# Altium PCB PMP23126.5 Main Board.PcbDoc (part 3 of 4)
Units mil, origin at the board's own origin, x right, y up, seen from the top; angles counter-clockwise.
Board outline 7480.32 x 4667 mil, 6 copper layers (Top Layer, Signal Layer 1, Signal Layer 2, Signal Layer 3, Signal Layer 4, Bottom Layer), stack 65.8 mil thick; 166 components, 83 nets, 633 pads, 4418 vias.
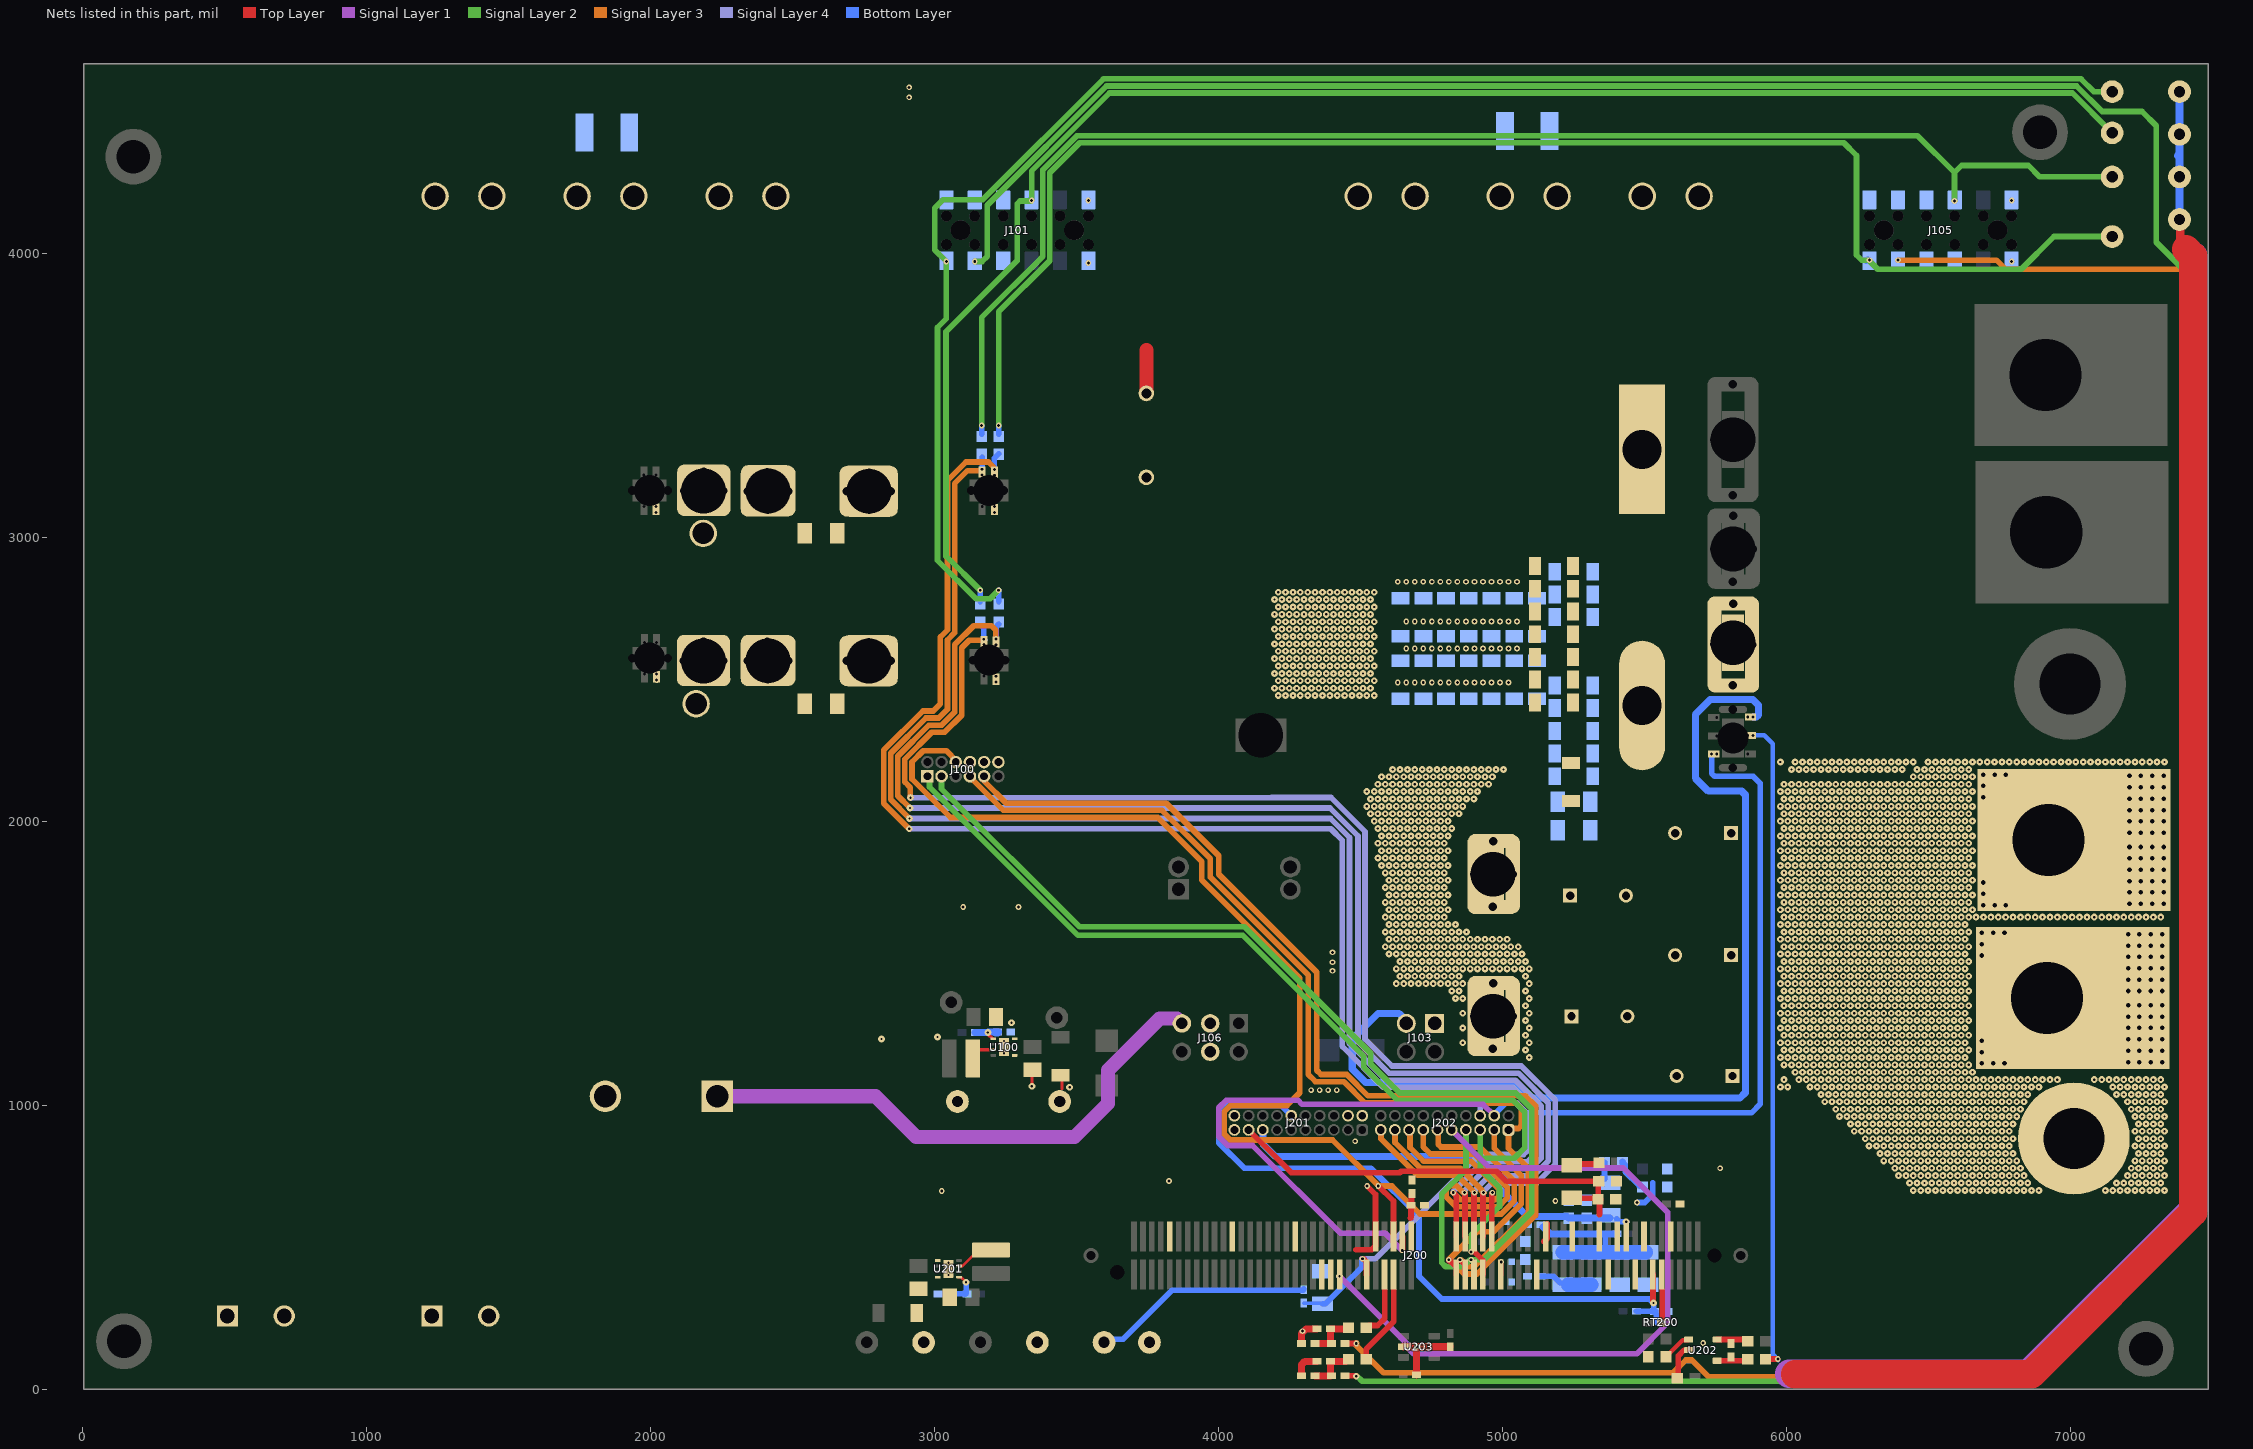
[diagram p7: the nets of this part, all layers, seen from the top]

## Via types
v1: diameter 24, hole 8, Top Layer to Bottom Layer, 3810 vias
v2: diameter 32, hole 16, Top Layer to Bottom Layer, 232 vias
v3: diameter 24, hole 8, Top Layer to Bottom Layer, tented top, 210 vias
v4: diameter 20, hole 10, Top Layer to Bottom Layer, 76 vias
v5: diameter 20, hole 10, Top Layer to Bottom Layer, tented top, 57 vias
v6: diameter 24, hole 8, Top Layer to Bottom Layer, tented both sides, 29 vias
v7: diameter 19.68, hole 7.87, Top Layer to Bottom Layer, 4 vias

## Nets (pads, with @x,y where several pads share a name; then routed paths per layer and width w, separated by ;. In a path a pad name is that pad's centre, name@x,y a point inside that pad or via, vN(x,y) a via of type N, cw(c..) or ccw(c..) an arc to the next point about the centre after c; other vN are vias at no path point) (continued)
Iout_SNS: C300.1 C301.1 C302.1 C303.1 C304.1 C305.1 C306.1 C307.1 C308.1 C309.1 C310.2 C311.2 C312.2 C313.2 C314.2 C315.1 C316.1 C317.1 C318.1 C319.1 C320.1 C321.1 C322.1 C323.1 C324.1 C325.1 C326.1 C327.1 C328.1 C329.1 C330.1 C331.1 C332.1 C333.1 C334.1 L100.2 pad.1@4900,1815 pad.1@4965,1700 pad.1@4965,1815 pad.1@4966,1932 pad.1@5035,1815 pad.1@5745,2625 pad.1@5810,2480 pad.1@5810,2630 pad.1@5811,2768 pad.1@5862,2303.04 pad.1@5877.57,2622.15 R102.2 R103.2 R226.1 | length 2304
  Top Layer w20: R226.1@5924.86,108.3 v4(5968.17,108.3)
  Bottom Layer w16: pad.1@5880,2305 5920,2305 5950,2275 5950,125 v4@5970,105
  other v4: 5880,2303.04
  other v5: 4660,2610 4690,2610 4720,2610 4750,2610 4780,2610 4810,2610 4840,2610 4870,2610 4900,2610 4930,2610 4960,2610 4990,2610 5020,2610 5050,2610 4660,2705 4690,2705 4720,2705 4750,2705 4780,2705 4810,2705 4840,2705 4870,2705 4900,2705 4930,2705 4960,2705 4990,2705 5020,2705 5050,2705
LEG1_FLT: J101.3 R200.2 | length 11737.8
  Top Layer w20: R200.2@4444.54,49.24 v6@4483.91,49.24
  Signal Layer 2 w20: v4(3141,3972) 3167,3972 3185,3990 3185,4170.36 3604.64,4590 7020,4590 7110,4500 7250,4500 7300,4450 7300,4040 7455,3885 7455,615 6870,30 4505,30 v6@4485,50
  other v6: 4484,48
LEG1_HS: J200.49 J202.17 pad.1@3172.91,2623.88 R105.2 | length 5044.8
  Top Layer w20: J200.49@4929.94,539.86 4929.94,692.57 v4(4931.63,694.27)
  Signal Layer 3 w20: v6(2914.78,2084.78) 2914.01,2085.54 2914.01,2120.49 2895,2139.5 2895,2220.36 2989.64,2315 3035,2315 3095,2375 3095,2612.43 3121.57,2639 pad.1@3170.41,2639 ; J202.17@4620,915 4620,870.54 4710.54,780 4849.76,780 4925.13,704.62 4925.13,700.76 v4(4931.63,694.27)
  Signal Layer 4 w20: v6(2914.78,2084.78) 4186.53,2084.78 4186.75,2085 4395,2085 4515,1965 4515,1235 4610,1140 5065,1140 5185,1020 5185,795 5118.25,728.25 4961.75,728.25 4935,701.5 v4@4935,700 ; pad.1@3172.91,2623.88 pad.1@3172.91,2642 ; pad.1@3172.91,2642.1 v6(3173,2642) pad.1@3175,2640
  Bottom Layer w20: R105.2@3165,2690 3173,2682 v6(3173,2642)
LEG1_HS1: J101.8 LEG1_HS.1 R105.1 | length 5683.7
  Signal Layer 2 w20: v4(3160,2815) 3040,2935 3040,3725 3290,3975 3290,4175 3300,4185 v4@3340,4185 ; v4(3341,4187) 3341,4291 3615,4565 7005,4565 LEG1_HS.1@7140,4430
  Bottom Layer w20: R105.1@3160,2775 v4(3160,2815) ; J101.8@3339.25,4194.75 J101.8@3342,4192
LEG1_HS_Fault: J101.6
LEG1_HS_OC: J101.4
LEG1_HS_TEMP: J101.2
LEG1_LS: J200.51 J202.19 pad.1@3215.96,2622.88 R104.1 | length 5164.4
  Top Layer w20: J200.51@4898.44,539.86 v4@4898.44,692.57
  Signal Layer 3 w20: v6(2913.08,2048.29) 2870,2091.37 2870,2230.71 2979.29,2340 3024.64,2340 3070,2385.36 3070,2622.78 3137.22,2690 3200,2690 3215,2675 pad.1@3215,2650 ; J202.19@4570,910 4570.83,909.17 4570.83,884.17 4637,818 4637.18,818 4653,802.18 4700.18,755 4839.4,755 v4(4900.13,694.27)
  Signal Layer 4 w20: v6(2913.08,2048.29) 4391.71,2048.29 4490,1950 4490,1224.64 4599.64,1115 5054.64,1115 ; v4@4900,695 4900,701.85 4951.4,753.25 5107.89,753.25 5160,805.36 5160,1009.64 5054.82,1114.82 5054.64,1114.82
  Bottom Layer w20: v4(3215.96,2643) 3215.96,2685.96 R104.1@3225,2695
LEG1_LS1: J101.1 LEG1_LS.1 R104.2 | length 5940.3
  Signal Layer 2 w20: v4(3225,2815) 3195,2785 3145,2785 3010,2920 3010,3740 3041,3771 v4(3041,3972) 3000,4013 3000,4160 3030,4190 3169.29,4190 3594.29,4615 7035,4615 7080,4570 LEG1_LS.1@7140,4570
  Bottom Layer w20: R104.2@3225,2775 v4(3225,2815)
LEG1_LS_OC: J101.5
LEG2_FLT: J105.3 R203.2 | length 7679.5
  Top Layer w20: R203.2@4444.54,163.42 v4@4479.98,163.42
  Signal Layer 3 w20: v4@4485,165 4485,155 4580,60 5600,60 5645,105 5665,105 5725,45 6854.64,45 7430,620.36 7430,3929.64 7414.64,3945 6770,3945 6738,3977 v4(6391,3977)
  other v4: 4483.91,163.42
LEG2_HS: J200.53 J202.13 pad.1@3166.91,3220.88 R108.2 | length 6028.7
  Top Layer w20: v4(4864.7,694.27) 4866.94,692.02 J200.53@4866.94,539.86
  Signal Layer 3 w20: v6(2911.59,2011.59) 2845,2078.18 2845,2241.07 2968.93,2365 3014.29,2365 3045,2395.71 3045,2640 3070,2665 3070,3190.43 3115.57,3236 pad.1@3164.41,3236 ; J202.13@4715.14,910 4720,905.14 4720,855 4745,830 4898.1,830 5015,713.1 5015,675.43 4983.84,644.27 4835.73,644.27 4800.33,679.67 4800.33,704.62 4814.98,719.27 4835.69,719.27 4860.69,694.27 v4(4864.7,694.27)
  Signal Layer 4 w20: v6(2911.59,2011.59) 4393.05,2011.59 4460,1944.64 4460,1219.29 4589.29,1090 5043.93,1090 5135,998.93 5135,815.71 5097.54,778.25 4941.04,778.25 4865,702.21 v4@4865,695
  Bottom Layer w20: pad.1@3166.91,3220.88 v4(3166.91,3241) R108.2@3166.91,3283.1
LEG2_HS1: J105.8 LEG2_HS.1 R108.1 | length 5014.3
  Signal Layer 2 w20: v4(3165,3395) 3165,3775 3380,3990 3380,4294.64 3500.36,4415 6460,4415 6590,4285 ; v4(6590,4185) 6590,4285 ; LEG2_HS.1@7145,4270 6890,4270 6850,4310 6615,4310 6590,4285
  Bottom Layer w20: R108.1@3165,3365 v4(3165,3395)
LEG2_HS_Fault: J105.6
LEG2_HS_OC: J105.4
LEG2_HS_TEMP: J105.2
LEG2_LS: J200.55 J202.15 pad.1@3209.96,3219.88 R106.1 | length 5987.2
  Top Layer w20: v4(4825.33,694.27) 4835.45,684.15 J200.55@4835.45,539.86
  Signal Layer 3 w20: v6(2910,1975) 2820,2065 2820,2251.42 2958.58,2390 2995,2390 3020,2415 3020,2650.36 3045,2675.36 3045,3200.78 3110.22,3266 3189,3266 pad.1@3210,3245 ; J202.15@4665,905 4672.95,897.05 4672.95,852.95 4720.89,805 4887.75,805 4988.13,704.62 4988.13,683.91 4973.48,669.27 4850.33,669.27 v4(4825.33,694.27)
  Signal Layer 4 w20: v6(2910,1975) 4394.29,1975 4435,1934.29 4435,1208.93 4578.93,1065 5033.58,1065 5110,988.58 5110,826.07 5087.18,803.25 4930.69,803.25 4825,697.56 v4@4825,695 ; v4(4825.33,694.27) v4@4825.53,694.47
  Bottom Layer w20: pad.1@3209.96,3219.88 v4(3209.96,3240) 3209.96,3279.96 R106.1@3225,3295
LEG2_LS1: J105.1 LEG2_LS.1 R106.2 | length 5221.9
  Signal Layer 2 w20: v4(3225,3395) 3225,3795 3405,3975 3405,4284.29 3510.71,4390 6200,4390 6245,4345 6245,3995 6263,3977 v4(6291,3977) ; v4@6290,3975 6320,3945 6825,3945 6940,4060 LEG2_LS.1@7145,4060
  Bottom Layer w20: R106.2@3225,3365 v4(3225,3395) ; J105.1@6279,3974 J105.1@6284,3979
LEG2_LS_OC: J105.5
LEG2_LS_TEMP: J105.7
LEG3_HS: J100.1 J200.50 J202.5 | length 3533
  Top Layer w20: v4(4888.32,485.61) 4900.13,485.61 4929.94,455.8 J200.50@4929.94,406
  Signal Layer 2 w20: J100.1@2974,2160 2981.75,2152.25 2981.75,2122.39 3504.14,1600 4084.64,1600 4510,1174.64 4510,1136.86 4626.86,1020 5035,1020 5076.72,978.28 5076.72,851.72 5040,815 4920,815 ; v4(4888.32,485.61) 4888.32,545.21 4988.13,645.02 4988.13,711.87 4920,780 4920,815 ; J202.5@4920,915 4920,815
LEG3_LS: J100.3 J200.52 J202.7 | length 3918
  Top Layer w20: J200.52@4898.44,406 J200.52@4898.44,449.12
  Signal Layer 2 w20: J100.3@3024,2160 3024,2115.5 3509.5,1630 4090,1630 4535,1185 4535,1147.22 4637.22,1045 5045.36,1045 5101.72,988.64 5101.72,626.72 4933.05,458.05 v4(4888.32,458.05) ; J202.7@4875,910 4874.86,910 4870,905.14 4870,774.29 4784.58,688.88 4784.58,447.69 4799.23,433.05 4859.31,433.05 4884.31,458.05 v4@4886.95,458.05
LEG4_HS: J100.7 J200.54 J202.1 | length 3493.2
  Top Layer w20: v4(4848.95,458.05) 4866.94,440.06 J200.54@4866.94,406
  Signal Layer 3 w20: J100.7@3124,2160 3124,2157.61 3241.61,2040 3800,2040 3970,1870 3970,1805 4315,1460 4315,1110 4340,1085 4440,1085 4515,1010 5045,1010 5065,990 5065,930 5055,920 5030,920 J202.1@5025,915 ; v4(4848.95,458.05) 4852.97,458.05 4877.97,433.05 4898.68,433.05 5090,624.37 5090,780 5020,850 J202.1@5020,915 J202.1@5025,920
LEG4_LS: J100.9 J200.56 J202.3 | length 4168.3
  Top Layer w20: v4(4809.58,458.05) 4835.45,432.18 J200.56@4835.45,406
  Signal Layer 3 w20: J100.9@3175,2160 3175,2141.96 3251.96,2065 3815,2065 4000,1880 4000,1815 4345,1470 4345,1125 4360,1110 4450.36,1110 4525.36,1035 5080,1035 5115,1000 5115,614.01 4909.03,408.05 4863.6,408.05 4816.64,455 v4@4810,455 ; v4(4809.58,458.05) 4907.92,556.38 4966.66,556.38 5065,654.72 5065,755 4970,850 4970,910 J202.3@4975,915
NetC200_1: C200.1 R200.1 R201.2 R202.2 | length 153.5
  Top Layer w25: R202.2@4338.24,49.24 4365.8,49.24 R200.1@4393.36,49.24 ; R200.1@4393.36,57.12 C200.1@4393.36,100.43 R201.2@4448.48,100.43
NetC201_1: C201.1 R203.1 R204.2 R207.2 | length 153.5
  Top Layer w25: R207.2@4338.24,163.42 4365.8,163.42 4393.36,163.42 C201.1@4393.36,206.72 ; C201.1@4393.36,214.6 R204.2@4448.48,214.6
NetC203_1: C203.1 J200.57 R211.2 | length 88.4
  Top Layer w20: 4675,605 4676.38,606.38 C203.1@4676.38,650 ; C203.1@4680,650 4678.19,651.81 4678.19,689.57 R211.2@4680,691.38
NetC212_1: C212.1 R223.2 U202.5 | length 109.3
  Top Layer w20: U202.5@5754.58,177.2 R223.2@5863.83,177.2
NetC212_2: C212.2 R226.2 U202.4 | length 105.3
  Top Layer w20: U202.4@5754.58,102.39 R226.2@5859.9,102.39
NetD200_1: D200.1 D201.1 R206.1 R210.1 | length 3.9
  Bottom Layer w19.68: D201.1@5011.47,517.75 D201.1@5011.47,521.68
NetD202_2: D202.2 D203.2 R210.2 R212.1
NetJ200_62: J200.62 R201.1 | length 275.4
  Top Layer w20: R201.1@4519.35,116.17 4519.35,143.73 4616.08,240.46 4616.08,351.53
NetJ200_64: J200.64 R204.1 | length 163.4
  Top Layer w20: R204.1@4531.16,226.41 4558.72,226.41 4584.58,252.28 4584.58,351.53
NetL101_1: L101.1 U100.7 | length 74.9
  Top Layer w12: L101.1@3133,1200 3136.13,1196.87 U100.7@3206.6,1196.87
NetL200_1: L200.1 U201.7 | length 69.2
  Top Layer w10: U201.7@3085.57,435.78 3098.01,435.78 L200.1@3138.17,475.94
NetPSON_1: PSON.1 R233.1 | length 782.1
  Bottom Layer w20: PSON.1@3596,167 3607.48,178.48 3663.72,178.48 3836.24,351 4297.06,351 4299,352.94 R233.1@4299,355
NetR107_1: R107.1 R109.2 U100.5 | length 114.6
  Top Layer w12: v6(3187,1258) 3189.3,1255.7 3189.3,1250.78 U100.5@3202.76,1237.32
  Bottom Layer w25: R107.1@3142.62,1258 v6@3186,1258 ; v6(3187,1258) 3188.31,1259.31 3219.69,1259.31 R109.2@3220.38,1260 ; R109.2@3215,1257 3222,1257 R109.2@3224,1259
NetR205_2: R205.2 R206.2 R208.2 R209.2 R234.2 R235.2 | length 625.5
  Bottom Layer w20: 5361,484.09 5361,547
  Bottom Layer w25: R206.2@5141.39,572.87 5165.02,549.24 R205.2@5401.24,549.24
  Bottom Layer w50: R209.2@5211,484.09 R208.2@5311,484.09 5361,484.09 R234.2@5411,484.09 R235.2@5503.91,484.09
NetR220_2: R220.2 R221.1 | length 59.1
  Bottom Layer w20: R220.2@5357.93,742.16 R221.1@5357.93,801.21
NetR224_1: R224.1 U202.1 | length 103.2
  Top Layer w16: R224.1@5574.46,116.17 5633.52,175.23 U202.1@5653.2,175.23
NetR228_2: R228.2 R229.1 | length 108.5
  Top Layer w20: R228.2@5232,793 5234.04,795.04 5334.04,795.04 R229.1@5338,799
NetR230_1: R230.1 R232.2 U201.5 | length 120.2
  Top Layer w10: U201.5@3085.57,396.41 3092.69,396.41 v6@3108.17,380.94
  Bottom Layer w20: R232.2@3058.28,337.71 3104.29,337.71 R230.1@3106,336 ; R230.1@3108,339 3110.25,339 3110.77,339.52 3110.77,378.23 v6(3110,379)
ORING_EN: J200.59 J202.4 pad.1@5753,2238.91 | length 4323.3
  Top Layer w20: v4(4646,491) 4646.47,491.47 J200.59@4646.47,539.86
  Signal Layer 1 w20: v4(4646,491) 4585.81,551.19 4427.9,551.19 4119.09,860 4031.72,860 4000,891.72 4000,993.28 4026.72,1020 4278.28,1020 4293.28,1005 4930.44,1005 4970,965.44 J202.4@4970,965
  Bottom Layer w20: J202.4@4965.22,970.22 J202.4@4965.44,970 ; J202.4@4975,975 5010,1010 5045,1010 5080,975 5875,975 5906,1006 5906,2135 5881,2160 5745,2160 5735,2170 v4(5735,2238.91)
PGND: C100.2 C101.2 C102.2 C103.2 C104.2 C105.1 C106.2 C107.2 C108.2 J106.3 J106.4 pad.1@2019.09,3110.12 pad.1@2021.09,2520.12 pad.1@2342,2566 pad.1@2342,3163 pad.1@2411,2633 pad.1@2411,3230 pad.1@2412,2502 pad.1@2412,3099 pad.1@2413,2567 pad.1@2413,3164 pad.1@2485,2567 pad.1@2485,3164 PGND.1 PGND.2 R109.1 TP107.1 TP108.1 TP113.1 TP114.1 U100.1 U100.4 U100.9@3244,1206.72 | length 260.3
  Top Layer w10: v6(3342,1069) 3342,1125 C106.2@3344,1127 ; C108.2@3443,1107.07 3448,1102.07 3448,1060
  Top Layer w50: C105.1@3745,3507.64 3745,3660
  other v4: 2021.09,2499 2019.09,3089
  other v6: 3475,1065 2813,1235 3010,1242 3270,1292
  other v7: 3244,1185.06 3244,1228.37
PRI_FAULT_SEC: J200.74 J202.9 | length 2590.9
  Signal Layer 1 w20: v6(4425,400) 4671.51,153.49 4671.51,141.25 4686.16,126.61 5471.61,126.61 5580,235 5580,625.36 5424.27,781.08 4953.47,781.08 4820,914.56 J202.9@4820,915
PSFB_ON: J200.68 J202.6 R225.2 R233.2 | length 1452.4
  Top Layer w20: v4(4505.63,461.72) 4508.28,461.72 4520,450 J200.68@4520,405
  Signal Layer 4 w20: v4(4505.63,461.72) 4551.72,461.72 4918.25,828.25 5073.25,828.25 5085,840 5085,975 5050,1010 4935,1010 4920,995 J202.6@4920,965
  Bottom Layer w12: R233.2@4298.87,305.15 4377.15,305.15 R225.2@4378,306
  Bottom Layer w20: R225.2@4365,302.91 4375.83,302.91 4504.45,431.54 v4@4504.45,460.73
PWM_ACL: J100.6 J200.61 J202.11 | length 4522.4
  Top Layer w20: v4(4561.55,717.89) 4614.98,664.46 J200.61@4614.98,539.86
  Signal Layer 2 w20: J100.6@3074,2210 J100.6@3074,2212.39
  Signal Layer 3 w20: 3005,2065 3010,2060 ; J100.6@3074,2210 J100.6@3074,2212.39 ; J100.6@3078,2214 3076.52,2214 3041,2249.52 2959.52,2249.52 2920,2210 2920,2149.85 3009.85,2060 3010,2060 ; v4@4560,720 4400.67,879.33 4040.23,879.33 4019.33,900.23 4019.33,979.77 4040.23,1000.67 4240,1000.67 4285,1045.67 4285,1450 3940,1795 3940,1860 3785,2015 3055,2015 3010,2060 ; v4(4561.55,717.89) 4609.93,717.89 4708.55,619.27 4994.19,619.27 5040,665.08 5040,735 4920,855 4781.72,855 4772.39,864.33 4772.39,907.61 J202.11@4770,910
PWM_DEBUG_SEC: R211.1
SEC_SCI_RX0: J200.76
SEC_SCI_TX0: J200.78
SGND: C105.2 C200.2 C201.2 C202.2 C203.2 C205.2 C210.2 C211.1 C213.2 C214.2 C215.2 C216.2 C217.2 C218.2 C219.2 C300.2 C301.2 C302.2 C303.2 C304.2 C305.2 C306.2 C307.2 C308.2 C309.2 C310.1 C311.1 C312.1 C313.1 C314.1 C315.2 C316.2 C317.2 C318.2 C319.2 C320.2 C321.2 C322.2 C323.2 C324.2 C325.2 C326.2 C327.2 C328.2 C329.2 C330.2 C331.2 C332.2 C333.2 C334.2 J100.8 J100.10 J100.12 J101.11 J101.12 J103.1 J103.3 J104.1 J105.11 J105.12 J200.7 J200.10 J200.13 J200.16 J200.19 J200.22 J200.29 J200.35 J200.38 J200.46 J200.47 J200.65 J200.83 J200.97 J200.111 J201.2 J201.4 J201.19 J201.20 pad.1@3210.09,3109.12 pad.1@3216.09,2512.12 pad.1@4900,1315 pad.1@4965,1200 pad.1@4965,1315 pad.1@4966,1432 pad.1@5035,1315 pad.1@5862,2368.04 R101.1 R102.1 R103.1 R202.1 R207.1 R208.1 R209.1 R212.2 R222.1 R225.1 R227.1 R231.1 R232.1 R234.1 R235.1 RT200.1 SGND101.1 SGND102.1 SGND103.1 SGND.1 T102.1 T103.1 U201.1 U201.4 U201.9@3048.17,425.94 U202.2 U203.2 | length 15713.4
  Top Layer w20: 4482.81,493.48 4537.93,493.48 4551.98,507.54 J200.65@4551.98,539.86 4551.98,688.09 v4(4522.18,717.89) ; J200.47@4961.43,539.86 4961.43,692.57 v4(4963.13,694.27) ; J200.46@4992.93,406 J200.46@4992.93,448.48 ; J200.35@5144.56,522.1 J200.35@5156.37,533.91 ; J200.35@5150.41,527.95 J200.35@5156.37,533.91 ; J200.35@5156.37,585.09 J200.35@5156.37,533.91 ; C213.2@5560.96,240.46 5560.96,351.53 ; C211.1@5617.77,49.24 5617.77,120.11 5637.46,139.8 U202.2@5654.19,139.8
  Top Layer w25: R202.1@4291,53.18 4291,88.61 4302.81,100.43 C200.2@4346.12,100.43 ; R207.1@4291,167.35 4291,198.85 4306.75,214.6 C201.2@4346.12,214.6 ; U203.2@4650.25,151.61 v4(4696.51,151.61) C217.2@4814.62,151.61 ; C218.2@4696.51,53.18 v4@4696.51,147.67
  Top Layer w29.53: SGND102.1@7382,4120 7385,4117 7385,4015
  Top Layer w100: 6030,55 6860,55 7430,625 7430,3990 7405,4015
  Signal Layer 1 w100: 6008.4,56.61 6851.6,56.61 7430,635 7430,3990
  Signal Layer 3 w29.53: SGND.1@2959.86,180.23 SGND.1@2961,179.09 ; SGND.1@2961,167 SGND.1@2961,179.09 ; SGND.1@2971.67,168.42 SGND.1@2961,179.09
  Bottom Layer w20: R212.2@5133.52,399.64 5178.36,399.64 R209.1@5201,377 ; v4@5476.04,659.48 5499.66,659.48 5527.49,687.31 5527.49,728.49
  Bottom Layer w25: J103.3@4660,1300 4635,1325 4560,1325 4470,1235 4470,1130 4517.5,1082.5 5046.75,1082.5 5101.75,1027.5 5835,1027.5 5853.5,1046 5853.5,2095 5841,2107.5 5723.25,2107.5 5677.5,2153.25 5677.5,2377.5 5730,2430 5880,2430 5900,2410 5900,2375 5893.04,2368.04 v4(5880,2368.04)
  Bottom Layer w29.53: 7377,4345 7382,4350 ; SGND102.1@7382,4120 SGND101.1@7382,4270 7382,4350 ; SGND.1@7382,4570 SGND103.1@7382,4420 7382,4350
  Bottom Layer w50: R209.1@5228.91,369.91 R208.1@5311,369.91
  other v1: 6445,702 6471,702 6497,702 6523,702 6549,702 6575,702 6601,702 6627,702 6653,702 6679,702 6705,702 6731,702 6757,702 6783,702 6809,702 6835,702 6861,702 6887,702 7121,702 7147,702 7173,702 7199,702 7225,702 7251,702 7277,702 7303,702 7329,702 6432,728 6458,728 6484,728 6510,728 6536,728 6562,728 6588,728 6614,728 6640,728 6666,728 6692,728 6718,728 6744,728 6770,728 6796,728 6822,728 6848,728 7160,728 7186,728 7212,728 7238,728 7264,728 7290,728 7316,728 6393,754 6419,754 6445,754 6471,754 6497,754 6523,754 6549,754 6575,754 6601,754 6627,754 6653,754 6679,754 6705,754 6731,754 6757,754 6783,754 6809,754 6835,754 7199,754 7225,754 7251,754 7277,754 7303,754 7329,754 6380,780 6406,780 6432,780 6458,780 6484,780 6510,780 6536,780 6562,780 6588,780 6614,780 6640,780 6666,780 6692,780 6718,780 6744,780 6770,780 6796,780 6822,780 7212,780 7238,780 7264,780 7290,780 7316,780 6341,806 6367,806 6393,806 6419,806 6445,806 6471,806 6497,806 6523,806 6549,806 6575,806 6601,806 6627,806 6653,806 6679,806 6705,806 6731,806 6757,806 6783,806 6809,806 7225,806 7251,806 7277,806 7303,806 7329,806 6328,832 6354,832 6380,832 6406,832 6432,832 6458,832 6484,832 6510,832 6536,832 6562,832 6588,832 6614,832 6640,832 6666,832 6692,832 6718,832 6744,832 6770,832 6796,832 7238,832 7264,832 7290,832 7316,832 6289,858 6315,858 6341,858 6367,858 6393,858 6419,858 6445,858 6471,858 6497,858 6523,858 6549,858 6575,858 6601,858 6627,858 6653,858 6679,858 6705,858 6731,858 6757,858 6783,858 7225,858 7251,858 7277,858 7303,858 7329,858 6276,884 6302,884 6328,884 6354,884 6380,884 6406,884 6432,884 6458,884 6484,884 6510,884 6536,884 6562,884 6588,884 6614,884 6640,884 6666,884 6692,884 6718,884 6744,884 6770,884 6796,884 7238,884 7264,884 7290,884 7316,884 6237,910 6263,910 6289,910 6315,910 6341,910 6367,910 6393,910 6419,910 6445,910 6471,910 6497,910 6523,910 6549,910 6575,910 6601,910 6627,910 6653,910 6679,910 6705,910 6731,910 6757,910 6783,910 7225,910 7251,910 7277,910 7303,910 7329,910 6224,936 6250,936 6276,936 6302,936 6328,936 6354,936 6380,936 6406,936 6432,936 6458,936 6484,936 6510,936 6536,936 6562,936 6588,936 6614,936 6640,936 6666,936 6692,936 6718,936 6744,936 6770,936 6796,936 7238,936 7264,936 7290,936 7316,936 6185,962 6211,962 6237,962 6263,962 6289,962 6315,962 6341,962 6367,962 6393,962 6419,962 6445,962 6471,962 6497,962 6523,962 6549,962 6575,962 6601,962 6627,962 6653,962 6679,962 6705,962 6731,962 6757,962 6783,962 6809,962 7225,962 7251,962 7277,962 7303,962 7329,962 6172,988 6198,988 6224,988 6250,988 6276,988 6302,988 6328,988 6354,988 6380,988 6406,988 6432,988 6458,988 6484,988 6510,988 6536,988 6562,988 6588,988 6614,988 6640,988 6666,988 6692,988 6718,988 6744,988 6770,988 6796,988 6822,988 7212,988 7238,988 7264,988 7290,988 7316,988 6133,1014 6159,1014 6185,1014 6211,1014 6237,1014 6263,1014 6289,1014 6315,1014 6341,1014 6367,1014 6393,1014 6419,1014 6445,1014 6471,1014 6497,1014 6523,1014 6549,1014 6575,1014 6601,1014 6627,1014 6653,1014 6679,1014 6705,1014 6731,1014 6757,1014 6783,1014 6809,1014 6835,1014 7199,1014 7225,1014 7251,1014 7277,1014 7303,1014 7329,1014 6120,1040 6146,1040 6172,1040 6198,1040 6224,1040 6250,1040 6276,1040 6302,1040 6328,1040 6354,1040 6380,1040 6406,1040 6432,1040 6458,1040 6484,1040 6510,1040 6536,1040 6562,1040 6588,1040 6614,1040 6640,1040 6666,1040 6692,1040 6718,1040 6744,1040 6770,1040 6796,1040 6822,1040 6848,1040 7160,1040 7186,1040 7212,1040 7238,1040 7264,1040 7290,1040 7316,1040 5977,1066 6003,1066 6081,1066 6107,1066 6133,1066 6159,1066 6185,1066 6211,1066 6237,1066 6263,1066 6289,1066 6315,1066 6341,1066 6367,1066 6393,1066 6419,1066 6445,1066 6471,1066 6497,1066 6523,1066 6549,1066 6575,1066 6601,1066 6627,1066 6653,1066 6679,1066 6705,1066 6731,1066 6757,1066 6783,1066 6809,1066 6835,1066 6861,1066 6887,1066 7147,1066 7173,1066 7199,1066 7225,1066 7251,1066 7277,1066 7303,1066 7329,1066 5990,1092 6042,1092 6068,1092 6094,1092 6120,1092 6146,1092 6172,1092 6198,1092 6224,1092 6250,1092 6276,1092 6302,1092 6328,1092 6354,1092 6380,1092 6406,1092 6432,1092 6458,1092 6484,1092 6510,1092 6536,1092 6562,1092 6588,1092 6614,1092 6640,1092 6666,1092 6692,1092 6718,1092 6744,1092 6770,1092 6796,1092 6822,1092 6848,1092 6874,1092 6900,1092 6926,1092 6952,1092 7082,1092 7108,1092 7134,1092 7160,1092 7186,1092 7212,1092 7238,1092 7264,1092 7290,1092 7316,1092 6029,1118 6055,1118 6081,1118 6107,1118 6133,1118 6159,1118 6185,1118 6211,1118 6237,1118 6263,1118 6289,1118 6315,1118 6341,1118 6367,1118 6393,1118 6419,1118 6445,1118 6471,1118 6497,1118 6523,1118 6549,1118 6575,1118 6601,1118 6627,1118 6653,1118 5990,1144 6016,1144 6042,1144 6068,1144 6094,1144 6120,1144 6146,1144 6172,1144 6198,1144 6224,1144 6250,1144 6276,1144 6302,1144 6328,1144 6354,1144 6380,1144 6406,1144 6432,1144 6458,1144 6484,1144 6510,1144 6536,1144 6562,1144 6588,1144 6614,1144 6640,1144 5093,1170 5977,1170 6003,1170 6029,1170 6055,1170 6081,1170 6107,1170 6133,1170 6159,1170 6185,1170 6211,1170 6237,1170 6263,1170 6289,1170 6315,1170 6341,1170 6367,1170 6393,1170 6419,1170 6445,1170 6471,1170 6497,1170 6523,1170 6549,1170 6575,1170 6601,1170 6627,1170 5080,1196 5990,1196 6016,1196 6042,1196 6068,1196 6094,1196 6120,1196 6146,1196 6172,1196 6198,1196 6224,1196 6250,1196 6276,1196 6302,1196 6328,1196 6354,1196 6380,1196 6406,1196 6432,1196 6458,1196 6484,1196 6510,1196 6536,1196 6562,1196 6588,1196 6614,1196 6640,1196 4859,1222 5093,1222 5977,1222 6003,1222 6029,1222 6055,1222 6081,1222 6107,1222 6133,1222 6159,1222 6185,1222 6211,1222 6237,1222 6263,1222 6289,1222 6315,1222 6341,1222 6367,1222 6393,1222 6419,1222 6445,1222 6471,1222 6497,1222 6523,1222 6549,1222 6575,1222 6601,1222 6627,1222 5080,1248 5990,1248 6016,1248 6042,1248 6068,1248 6094,1248 6120,1248 6146,1248 6172,1248 6198,1248 6224,1248 6250,1248 6276,1248 6302,1248 6328,1248 6354,1248 6380,1248 6406,1248 6432,1248 6458,1248 6484,1248 6510,1248 6536,1248 6562,1248 6588,1248 6614,1248 6640,1248 4859,1274 5093,1274 5977,1274 6003,1274 6029,1274 6055,1274 6081,1274 6107,1274 6133,1274 6159,1274 6185,1274 6211,1274 6237,1274 6263,1274 6289,1274 6315,1274 6341,1274 6367,1274 6393,1274 6419,1274 6445,1274 6471,1274 6497,1274 6523,1274 6549,1274 6575,1274 6601,1274 6627,1274 5080,1300 5990,1300 6016,1300 6042,1300 6068,1300 6094,1300 6120,1300 6146,1300 6172,1300 6198,1300 6224,1300 6250,1300 6276,1300 6302,1300 6328,1300 6354,1300 6380,1300 6406,1300 6432,1300 6458,1300 6484,1300 6510,1300 6536,1300 6562,1300 6588,1300 6614,1300 6640,1300 4859,1326 5093,1326 5977,1326 6003,1326 6029,1326 6055,1326 6081,1326 6107,1326 6133,1326 6159,1326 6185,1326 6211,1326 6237,1326 6263,1326 6289,1326 6315,1326 6341,1326 6367,1326 6393,1326 6419,1326 6445,1326 6471,1326 6497,1326 6523,1326 6549,1326 6575,1326 6601,1326 6627,1326 5080,1352 5990,1352 6016,1352 6042,1352 6068,1352 6094,1352 6120,1352 6146,1352 6172,1352 6198,1352 6224,1352 6250,1352 6276,1352 6302,1352 6328,1352 6354,1352 6380,1352 6406,1352 6432,1352 6458,1352 6484,1352 6510,1352 6536,1352 6562,1352 6588,1352 6614,1352 6640,1352 4833,1378 4859,1378 5093,1378 5977,1378 6003,1378 6029,1378 6055,1378 6081,1378 6107,1378 6133,1378 6159,1378 6185,1378 6211,1378 6237,1378 6263,1378 6289,1378 6315,1378 6341,1378 6367,1378 6393,1378 6419,1378 6445,1378 6471,1378 6497,1378 6523,1378 6549,1378 6575,1378 6601,1378 6627,1378 4820,1404 4846,1404 5080,1404 5990,1404 6016,1404 6042,1404 6068,1404 6094,1404 6120,1404 6146,1404 6172,1404 6198,1404 6224,1404 6250,1404 6276,1404 6302,1404 6328,1404 6354,1404 6380,1404 6406,1404 6432,1404 6458,1404 6484,1404 6510,1404 6536,1404 6562,1404 6588,1404 6614,1404 6640,1404 4625,1430 4651,1430 4677,1430 4703,1430 4729,1430 4755,1430 4781,1430 4807,1430 4833,1430 4859,1430 5093,1430 5977,1430 6003,1430 6029,1430 6055,1430 6081,1430 6107,1430 6133,1430 6159,1430 6185,1430 6211,1430 6237,1430 6263,1430 6289,1430 6315,1430 6341,1430 6367,1430 6393,1430 6419,1430 6445,1430 6471,1430 6497,1430 6523,1430 6549,1430 6575,1430 6601,1430 6627,1430 4638,1456 4664,1456 4690,1456 4716,1456 4742,1456 4768,1456 4794,1456 4820,1456 4846,1456 5080,1456 5990,1456 6016,1456 6042,1456 6068,1456 6094,1456 6120,1456 6146,1456 6172,1456 6198,1456 6224,1456 6250,1456 6276,1456 6302,1456 6328,1456 6354,1456 6380,1456 6406,1456 6432,1456 6458,1456 6484,1456 6510,1456 6536,1456 6562,1456 6588,1456 6614,1456 6640,1456 4625,1482 4651,1482 4677,1482 4703,1482 4729,1482 4755,1482 4781,1482 4807,1482 4833,1482 4859,1482 4885,1482 4911,1482 4937,1482 4963,1482 4989,1482 5015,1482 5041,1482 5067,1482 5093,1482 5977,1482 6003,1482 6029,1482 6055,1482 6081,1482 6107,1482 6133,1482 6159,1482 6185,1482 6211,1482 6237,1482 6263,1482 6289,1482 6315,1482 6341,1482 6367,1482 6393,1482 6419,1482 6445,1482 6471,1482 6497,1482 6523,1482 6549,1482 6575,1482 6601,1482 6627,1482 4638,1508 4664,1508 4690,1508 4716,1508 4742,1508 4768,1508 4794,1508 4820,1508 4846,1508 4872,1508 4898,1508 4924,1508 4950,1508 4976,1508 5002,1508 5028,1508 5054,1508 5080,1508 5990,1508 6016,1508 6042,1508 6068,1508 6094,1508 6120,1508 6146,1508 6172,1508 6198,1508 6224,1508 6250,1508 6276,1508 6302,1508 6328,1508 6354,1508 6380,1508 6406,1508 6432,1508 6458,1508 6484,1508 6510,1508 6536,1508 6562,1508 6588,1508 6614,1508 6640,1508 4599,1534 4625,1534 4651,1534 4677,1534 4703,1534 4729,1534 4755,1534 4781,1534 4807,1534 4833,1534 4859,1534 4885,1534 4911,1534 4937,1534 4963,1534 4989,1534 5015,1534 5041,1534 5067,1534 5977,1534 6003,1534 6029,1534 6055,1534 6081,1534 6107,1534 6133,1534 6159,1534 6185,1534 6211,1534 6237,1534 6263,1534 6289,1534 6315,1534 6341,1534 6367,1534 6393,1534 6419,1534 6445,1534 6471,1534 6497,1534 6523,1534 6549,1534 6575,1534 6601,1534 6627,1534 4586,1560 4612,1560 4638,1560 4664,1560 4690,1560 4716,1560 4742,1560 4768,1560 4794,1560 4820,1560 4846,1560 4872,1560 4898,1560 4924,1560 4950,1560 4976,1560 5002,1560 5028,1560 5054,1560 5990,1560 6016,1560 6042,1560 6068,1560 6094,1560 6120,1560 6146,1560 6172,1560 6198,1560 6224,1560 6250,1560 6276,1560 6302,1560 6328,1560 6354,1560 6380,1560 6406,1560 6432,1560 6458,1560 6484,1560 6510,1560 6536,1560 6562,1560 6588,1560 6614,1560 6640,1560 4599,1586 4625,1586 4651,1586 4677,1586 4703,1586 4729,1586 4755,1586 4781,1586 4807,1586 4833,1586 4859,1586 4885,1586 4911,1586 4937,1586 4963,1586 4989,1586 5015,1586 5977,1586 6003,1586 6029,1586 6055,1586 6081,1586 6107,1586 6133,1586 6159,1586 6185,1586 6211,1586 6237,1586 6263,1586 6289,1586 6315,1586 6341,1586 6367,1586 6393,1586 6419,1586 6445,1586 6471,1586 6497,1586 6523,1586 6549,1586 6575,1586 6601,1586 6627,1586 4586,1612 4612,1612 4638,1612 4664,1612 4690,1612 4716,1612 4742,1612 4768,1612 4794,1612 4820,1612 4846,1612 4872,1612 5990,1612 6016,1612 6042,1612 6068,1612 6094,1612 6120,1612 6146,1612 6172,1612 6198,1612 6224,1612 6250,1612 6276,1612 6302,1612 6328,1612 6354,1612 6380,1612 6406,1612 6432,1612 6458,1612 6484,1612 6510,1612 6536,1612 6562,1612 6588,1612 6614,1612 6640,1612 4599,1638 4625,1638 4651,1638 4677,1638 4703,1638 4729,1638 4755,1638 4781,1638 4807,1638 4833,1638 5977,1638 6003,1638 6029,1638 6055,1638 6081,1638 6107,1638 6133,1638 6159,1638 6185,1638 6211,1638 6237,1638 6263,1638 6289,1638 6315,1638 6341,1638 6367,1638 6393,1638 6419,1638 6445,1638 6471,1638 6497,1638 6523,1638 6549,1638 6575,1638 6601,1638 6627,1638 4586,1664 4612,1664 4638,1664 4664,1664 4690,1664 4716,1664 4742,1664 4768,1664 4794,1664 5990,1664 6016,1664 6042,1664 6068,1664 6094,1664 6120,1664 6146,1664 6172,1664 6198,1664 6224,1664 6250,1664 6276,1664 6302,1664 6328,1664 6354,1664 6380,1664 6406,1664 6432,1664 6458,1664 6484,1664 6510,1664 6536,1664 6562,1664 6588,1664 6614,1664 6640,1664 6666,1664 6692,1664 6718,1664 6744,1664 6770,1664 6796,1664 6822,1664 6848,1664 6874,1664 6900,1664 6926,1664 6952,1664 6978,1664 7004,1664 7030,1664 7056,1664 7082,1664 7108,1664 7134,1664 7160,1664 7186,1664 7212,1664 7238,1664 7264,1664 7290,1664 7316,1664 4599,1690 4625,1690 4651,1690 4677,1690 4703,1690 4729,1690 4755,1690 4781,1690 4807,1690 5977,1690 6003,1690 6029,1690 6055,1690 6081,1690 6107,1690 6133,1690 6159,1690 6185,1690 6211,1690 6237,1690 6263,1690 6289,1690 6315,1690 6341,1690 6367,1690 6393,1690 6419,1690 6445,1690 6471,1690 6497,1690 6523,1690 6549,1690 6575,1690 6601,1690 6627,1690 6653,1690 4586,1716 4612,1716 4638,1716 4664,1716 4690,1716 4716,1716 4742,1716 4768,1716 4794,1716 5990,1716 6016,1716 6042,1716 6068,1716 6094,1716 6120,1716 6146,1716 6172,1716 6198,1716 6224,1716 6250,1716 6276,1716 6302,1716 6328,1716 6354,1716 6380,1716 6406,1716 6432,1716 6458,1716 6484,1716 6510,1716 6536,1716 6562,1716 6588,1716 6614,1716 6640,1716 4599,1742 4625,1742 4651,1742 4677,1742 4703,1742 4729,1742 4755,1742 4781,1742 4807,1742 5977,1742 6003,1742 6029,1742 6055,1742 6081,1742 6107,1742 6133,1742 6159,1742 6185,1742 6211,1742 6237,1742 6263,1742 6289,1742 6315,1742 6341,1742 6367,1742 6393,1742 6419,1742 6445,1742 6471,1742 6497,1742 6523,1742 6549,1742 6575,1742 6601,1742 6627,1742 6653,1742 4586,1768 4612,1768 4638,1768 4664,1768 4690,1768 4716,1768 4742,1768 4768,1768 4794,1768 5990,1768 6016,1768 6042,1768 6068,1768 6094,1768 6120,1768 6146,1768 6172,1768 6198,1768 6224,1768 6250,1768 6276,1768 6302,1768 6328,1768 6354,1768 6380,1768 6406,1768 6432,1768 6458,1768 6484,1768 6510,1768 6536,1768 6562,1768 6588,1768 6614,1768 6640,1768 4599,1794 4625,1794 4651,1794 4677,1794 4703,1794 4729,1794 4755,1794 4781,1794 4807,1794 5977,1794 6003,1794 6029,1794 6055,1794 6081,1794 6107,1794 6133,1794 6159,1794 6185,1794 6211,1794 6237,1794 6263,1794 6289,1794 6315,1794 6341,1794 6367,1794 6393,1794 6419,1794 6445,1794 6471,1794 6497,1794 6523,1794 6549,1794 6575,1794 6601,1794 6627,1794 6653,1794 4586,1820 4612,1820 4638,1820 4664,1820 4690,1820 4716,1820 4742,1820 4768,1820 4794,1820 5990,1820 6016,1820 6042,1820 6068,1820 6094,1820 6120,1820 6146,1820 6172,1820 6198,1820 6224,1820 6250,1820 6276,1820 6302,1820 6328,1820 6354,1820 6380,1820 6406,1820 6432,1820 6458,1820 6484,1820 6510,1820 6536,1820 6562,1820 6588,1820 6614,1820 6640,1820 4573,1846 4599,1846 4625,1846 4651,1846 4677,1846 4703,1846 4729,1846 4755,1846 4781,1846 4807,1846 5977,1846 6003,1846 6029,1846 6055,1846 6081,1846 6107,1846 6133,1846 6159,1846 6185,1846 6211,1846 6237,1846 6263,1846 6289,1846 6315,1846 6341,1846 6367,1846 6393,1846 6419,1846 6445,1846 6471,1846 6497,1846 6523,1846 6549,1846 6575,1846 6601,1846 6627,1846 6653,1846 4560,1872 4586,1872 4612,1872 4638,1872 4664,1872 4690,1872 4716,1872 4742,1872 4768,1872 4794,1872 5990,1872 6016,1872 6042,1872 6068,1872 6094,1872 6120,1872 6146,1872 6172,1872 6198,1872 6224,1872 6250,1872 6276,1872 6302,1872 6328,1872 6354,1872 6380,1872 6406,1872 6432,1872 6458,1872 6484,1872 6510,1872 6536,1872 6562,1872 6588,1872 6614,1872 6640,1872 4573,1898 4599,1898 4625,1898 4651,1898 4677,1898 4703,1898 4729,1898 4755,1898 4781,1898 4807,1898 5977,1898 6003,1898 6029,1898 6055,1898 6081,1898 6107,1898 6133,1898 6159,1898 6185,1898 6211,1898 6237,1898 6263,1898 6289,1898 6315,1898 6341,1898 6367,1898 6393,1898 6419,1898 6445,1898 6471,1898 6497,1898 6523,1898 6549,1898 6575,1898 6601,1898 6627,1898 6653,1898 4560,1924 4586,1924 4612,1924 4638,1924 4664,1924 4690,1924 4716,1924 4742,1924 4768,1924 4794,1924 5990,1924 6016,1924 6042,1924 6068,1924 6094,1924 6120,1924 6146,1924 6172,1924 6198,1924 6224,1924 6250,1924 6276,1924 6302,1924 6328,1924 6354,1924 6380,1924 6406,1924 6432,1924 6458,1924 6484,1924 6510,1924 6536,1924 6562,1924 6588,1924 6614,1924 6640,1924 4573,1950 4599,1950 4625,1950 4651,1950 4677,1950 4703,1950 4729,1950 4755,1950 4781,1950 4807,1950 5977,1950 6003,1950 6029,1950 6055,1950 6081,1950 6107,1950 6133,1950 6159,1950 6185,1950 6211,1950 6237,1950 6263,1950 6289,1950 6315,1950 6341,1950 6367,1950 6393,1950 6419,1950 6445,1950 6471,1950 6497,1950 6523,1950 6549,1950 6575,1950 6601,1950 6627,1950 6653,1950 4560,1976 4586,1976 4612,1976 4638,1976 4664,1976 4690,1976 4716,1976 4742,1976 4768,1976 4794,1976 4820,1976 5990,1976 6016,1976 6042,1976 6068,1976 6094,1976 6120,1976 6146,1976 6172,1976 6198,1976 6224,1976 6250,1976 6276,1976 6302,1976 6328,1976 6354,1976 6380,1976 6406,1976 6432,1976 6458,1976 6484,1976 6510,1976 6536,1976 6562,1976 6588,1976 6614,1976 6640,1976 4547,2002 4573,2002 4599,2002 4625,2002 4651,2002 4677,2002 4703,2002 4729,2002 4755,2002 4781,2002 4807,2002 5977,2002 6003,2002 6029,2002 6055,2002 6081,2002 6107,2002 6133,2002 6159,2002 6185,2002 6211,2002 6237,2002 6263,2002 6289,2002 6315,2002 6341,2002 6367,2002 6393,2002 6419,2002 6445,2002 6471,2002 6497,2002 6523,2002 6549,2002 6575,2002 6601,2002 6627,2002 6653,2002 4534,2028 4560,2028 4586,2028 4612,2028 4638,2028 4664,2028 4690,2028 4716,2028 4742,2028 4768,2028 4794,2028 4820,2028 4846,2028 5990,2028 6016,2028 6042,2028 6068,2028 6094,2028 6120,2028 6146,2028 6172,2028 6198,2028 6224,2028 6250,2028 6276,2028 6302,2028 6328,2028 6354,2028 6380,2028 6406,2028 6432,2028 6458,2028 6484,2028 6510,2028 6536,2028 6562,2028 6588,2028 6614,2028 6640,2028 4521,2054 4547,2054 4573,2054 4599,2054 4625,2054 4651,2054 4677,2054 4703,2054 4729,2054 4755,2054 4781,2054 4807,2054 4833,2054 4859,2054 5977,2054 6003,2054 6029,2054 6055,2054 6081,2054 6107,2054 6133,2054 6159,2054 6185,2054 6211,2054 6237,2054 6263,2054 6289,2054 6315,2054 6341,2054 6367,2054 6393,2054 6419,2054 6445,2054 6471,2054 6497,2054 6523,2054 6549,2054 6575,2054 6601,2054 6627,2054 6653,2054 4534,2080 4560,2080 4586,2080 4612,2080 4638,2080 4664,2080 4690,2080 4716,2080 4742,2080 4768,2080 4794,2080 4820,2080 4846,2080 4872,2080 4898,2080 5990,2080 6016,2080 6042,2080 6068,2080 6094,2080 6120,2080 6146,2080 6172,2080 6198,2080 6224,2080 6250,2080 6276,2080 6302,2080 6328,2080 6354,2080 6380,2080 6406,2080 6432,2080 6458,2080 6484,2080 6510,2080 6536,2080 6562,2080 6588,2080 6614,2080 6640,2080 4521,2106 4547,2106 4573,2106 4599,2106 4625,2106 4651,2106 4677,2106 4703,2106 4729,2106 4755,2106 4781,2106 4807,2106 4833,2106 4859,2106 4885,2106 4911,2106 5977,2106 6003,2106 6029,2106 6055,2106 6081,2106 6107,2106 6133,2106 6159,2106 6185,2106 6211,2106 6237,2106 6263,2106 6289,2106 6315,2106 6341,2106 6367,2106 6393,2106 6419,2106 6445,2106 6471,2106 6497,2106 6523,2106 6549,2106 6575,2106 6601,2106 6627,2106 6653,2106 4560,2132 4586,2132 4612,2132 4638,2132 4664,2132 4690,2132 4716,2132 4742,2132 4768,2132 4794,2132 4820,2132 4846,2132 4872,2132 4898,2132 4924,2132 4950,2132 5990,2132 6016,2132 6042,2132 6068,2132 6094,2132 6120,2132 6146,2132 6172,2132 6198,2132 6224,2132 6250,2132 6276,2132 6302,2132 6328,2132 6354,2132 6380,2132 6406,2132 6432,2132 6458,2132 6484,2132 6510,2132 6536,2132 6562,2132 6588,2132 6614,2132 6640,2132 4573,2158 4599,2158 4625,2158 4651,2158 4677,2158 4703,2158 4729,2158 4755,2158 4781,2158 4807,2158 4833,2158 4859,2158 4885,2158 4911,2158 4937,2158 4963,2158 6445,2158 6471,2158 6497,2158 6523,2158 6549,2158 6575,2158 6601,2158 6627,2158 6653,2158 4612,2184 4638,2184 4664,2184 4690,2184 4716,2184 4742,2184 4768,2184 4794,2184 4820,2184 4846,2184 4872,2184 4898,2184 4924,2184 4950,2184 4976,2184 5002,2184 6016,2184 6042,2184 6068,2184 6094,2184 6120,2184 6146,2184 6172,2184 6198,2184 6224,2184 6250,2184 6276,2184 6302,2184 6328,2184 6354,2184 6380,2184 6406,2184 6458,2184 6484,2184 6510,2184 6536,2184 6562,2184 6588,2184 6614,2184 6640,2184 5977,2210 6029,2210 6055,2210 6081,2210 6107,2210 6133,2210 6159,2210 6185,2210 6211,2210 6237,2210 6263,2210 6289,2210 6315,2210 6341,2210 6367,2210 6393,2210 6419,2210 6445,2210 6497,2210 6523,2210 6549,2210 6575,2210 6601,2210 6627,2210 6653,2210 6679,2210 6705,2210 6731,2210 6757,2210 6783,2210 6809,2210 6835,2210 6861,2210 6887,2210 6913,2210 6939,2210 6965,2210 6991,2210 7017,2210 7043,2210 7069,2210 7095,2210 7121,2210 7147,2210 7173,2210 7199,2210 7225,2210 7251,2210 7277,2210 7303,2210 7329,2210
  other v2: 6686,1149 6726,1149 6766,1149 7201,1154 7241,1154 7281,1154 7321,1154 6686,1189 7201,1194 7241,1194 7281,1194 7321,1194 6686,1229 7201,1234 7241,1234 7281,1234 7321,1234 7201,1274 7241,1274 7281,1274 7321,1274 7201,1314 7241,1314 7281,1314 7321,1314 7201,1354 7241,1354 7281,1354 7321,1354 7201,1404 7241,1404 7281,1404 7321,1404 7201,1444 7241,1444 7281,1444 7321,1444 7201,1484 7241,1484 7281,1484 7321,1484 7201,1524 7241,1524 7281,1524 7321,1524 6686,1529 7201,1564 7241,1564 7281,1564 7321,1564 6686,1569 7201,1604 7241,1604 7281,1604 7321,1604 6686,1609 6726,1609 6766,1609 6691,1706 6731,1706 6771,1706 7206,1711 7246,1711 7286,1711 7326,1711 6691,1746 7206,1751 7246,1751 7286,1751 7326,1751 6691,1786 7206,1791 7246,1791 7286,1791 7326,1791 7206,1831 7246,1831 7286,1831 7326,1831 7206,1871 7246,1871 7286,1871 7326,1871 7206,1911 7246,1911 7286,1911 7326,1911 7206,1961 7246,1961 7286,1961 7326,1961 7206,2001 7246,2001 7286,2001 7326,2001 7206,2041 7246,2041 7286,2041 7326,2041 7206,2081 7246,2081 7286,2081 7326,2081 6691,2086 7206,2121 7246,2121 7286,2121 7326,2121 6691,2126 7206,2161 7246,2161 7286,2161 7326,2161 6691,2166 6731,2166 6771,2166
  other v4: 5705,165 4294.94,206.72 4994.62,450.17 5472.1,659.48 5185,665 3025,700 3825,735 5765,780 4480,875 4325,1055 4355,1055 4385,1055 4415,1055 4400,1475 4400,1505 4400,1540 3100,1700 3295,1700 3216.09,2492 3210.09,3089 3541,3967 6791,3972 3541,4187 6791,4187 2910,4550 2910,4585
  other v5: 4630,2490 4660,2490 4690,2490 4720,2490 4750,2490 4780,2490 4810,2490 4840,2490 4870,2490 4900,2490 4930,2490 4960,2490 4990,2490 5020,2490 4630,2845 4660,2845 4690,2845 4720,2845 4750,2845 4780,2845 4810,2845 4840,2845 4870,2845 4900,2845 4930,2845 4960,2845 4990,2845 5020,2845 5050,2845
  other v7: 3048.17,404.28 3048.17,447.59
SWNODE1: pad.1@2117,2566 pad.1@2185.97,2565.41 pad.1@2186,2633 pad.1@2187,2502 pad.1@2255,2566 TP101.1
SWNODE1_1: TP105.1 TP106.1
SWNODE2: pad.1@2118,3165 pad.1@2185.97,3164.41 pad.1@2187,3232 pad.1@2188,3101 pad.1@2256,3165 TP100.1
SWNODE2_1: TP111.1 TP112.1
TMP_SEC: C205.1 J200.12 J201.12 R213.2 RT200.2 | length 2508.5
  Top Layer w20: J200.12@5528.36,406 5528.52,405.84 5528.52,308.56 5529.23,307.85 5529.23,307.23 v6@5529,307
  Bottom Layer w20: J201.12@4255,965 4255,965.44 4219.77,1000.67 4040.23,1000.67 4039.56,1000 4030,1000 4000,970 4000,870 4090,780 4534.8,780 4705,609.8 4705,400 4785,320 5514.92,320 5529.92,305 v6@5530,305 ; R213.2@5470.62,277 5471.12,276.5 C205.1@5530.77,276.5 ; v6(5530,306) 5530.77,305.23 C205.1@5530.77,276.5 ; C205.1@5530.77,276.23 C205.1@5533,274 ; C205.1@5534,272 5540.09,265.91 5540.09,239.81 5541.91,238 RT200.2@5543.2,238 ; C205.1@5538,277 5537.5,276.5 C205.1@5530.77,276.5
VBB: C100.1 C101.1 C102.1 C103.1 C104.1 J106.5 pad.1@2690,2566 pad.1@2690,3163 pad.1@2767,2632 pad.1@2768,2501 pad.1@2769,2566 pad.1@2769,3163 pad.1@2769,3229 pad.1@2770,3098 pad.1@2845,2566 pad.1@2845,3163 TP103.1 TP104.1 TP109.1 TP110.1 Vin.1 Vin.2 | length 1923.6
  Signal Layer 1 w50: C100.1@2235,1035 2236.54,1033.46 2791.28,1033.46 2934.75,890 3491.78,890 3610,1008.22 3610,1125.21 3792.27,1307.48 3851.21,1307.48 J106.5@3852.52,1306.17 ; J106.5@3867.14,1287.14 J106.5@3870,1290
VLV_FB: C214.1 J200.23 J201.17 R228.1 R231.2 | length 1528.9
  Top Layer w20: J201.17@4105,915 4105,914.56 4216.68,802.87 4255.56,764 4637.18,764 4642.55,769.37 4977.21,769.37 5012.58,734 R231.2@5337.5,734 5336,732.5 C214.1@5336,679 ; R228.1@5243,676.91 5245.96,673.96 5341.04,673.96 C214.1@5344,671 ; C214.1@5334.5,671 5340,665.5 5340,617 5339,616
VLV_FB1: C210.1 J200.17 J201.15 R220.1 R222.2 | length 1419.7
  Bottom Layer w20: R220.1@5401,602 5411,592 v6@5436,592
  Bottom Layer w25: J201.15@4155,915 4155,865 4199,821 4875.28,821 5086.23,610.05 5226.26,610.05 R222.2@5231.94,604.36 C210.1@5294.94,604.36 R220.1@5377.61,604.36
  other v6: 5434,592
Vout_SNS+: R100.2 R221.2 | length 114.8
  Bottom Layer w20: R221.2@5420.92,797 R221.2@5420.92,801.21 ; R221.2@5420.92,805.15 R221.2@5422.89,803.18 ; R221.2@5426,797 5431,792 5431,767 5481,717 R100.2@5486,717
Vout_SNS-: R101.2
VSR: L100.1
  other v3: 4209,2444 4235,2444 4261,2444 4287,2444 4313,2444 4339,2444 4365,2444 4391,2444 4417,2444 4443,2444 4469,2444 4495,2444 4521,2444 4547,2444 4196,2470 4222,2470 4248,2470 4274,2470 4300,2470 4326,2470 4352,2470 4378,2470 4404,2470 4430,2470 4456,2470 4482,2470 4508,2470 4534,2470 4209,2496 4235,2496 4261,2496 4287,2496 4313,2496 4339,2496 4365,2496 4391,2496 4417,2496 4443,2496 4469,2496 4495,2496 4521,2496 4547,2496 4196,2522 4222,2522 4248,2522 4274,2522 4300,2522 4326,2522 4352,2522 4378,2522 4404,2522 4430,2522 4456,2522 4482,2522 4508,2522 4534,2522 4209,2548 4235,2548 4261,2548 4287,2548 4313,2548 4339,2548 4365,2548 4391,2548 4417,2548 4443,2548 4469,2548 4495,2548 4521,2548 4547,2548 4196,2574 4222,2574 4248,2574 4274,2574 4300,2574 4326,2574 4352,2574 4378,2574 4404,2574 4430,2574 4456,2574 4482,2574 4508,2574 4534,2574 4209,2600 4235,2600 4261,2600 4287,2600 4313,2600 4339,2600 4365,2600 4391,2600 4417,2600 4443,2600 4469,2600 4495,2600 4521,2600 4547,2600 4196,2626 4222,2626 4248,2626 4274,2626 4300,2626 4326,2626 4352,2626 4378,2626 4404,2626 4430,2626 4456,2626 4482,2626 4508,2626 4534,2626 4209,2652 4235,2652 4261,2652 4287,2652 4313,2652 4339,2652 4365,2652 4391,2652 4417,2652 4443,2652 4469,2652 4495,2652 4521,2652 4547,2652 4196,2678 4222,2678 4248,2678 4274,2678 4300,2678 4326,2678 4352,2678 4378,2678 4404,2678 4430,2678 4456,2678 4482,2678 4508,2678 4534,2678 4209,2704 4235,2704 4261,2704 4287,2704 4313,2704 4339,2704 4365,2704 4391,2704 4417,2704 4443,2704 4469,2704 4495,2704 4521,2704 4547,2704 4196,2730 4222,2730 4248,2730 4274,2730 4300,2730 4326,2730 4352,2730 4378,2730 4404,2730 4430,2730 4456,2730 4482,2730 4508,2730 4534,2730 4209,2756 4235,2756 4261,2756 4287,2756 4313,2756 4339,2756 4365,2756 4391,2756 4417,2756 4443,2756 4469,2756 4495,2756 4521,2756 4547,2756 4196,2782 4222,2782 4248,2782 4274,2782 4300,2782 4326,2782 4352,2782 4378,2782 4404,2782 4430,2782 4456,2782 4482,2782 4508,2782 4534,2782 4209,2808 4235,2808 4261,2808 4287,2808 4313,2808 4339,2808 4365,2808 4391,2808 4417,2808 4443,2808 4469,2808 4495,2808 4521,2808 4547,2808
